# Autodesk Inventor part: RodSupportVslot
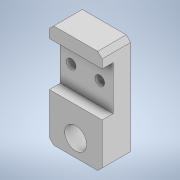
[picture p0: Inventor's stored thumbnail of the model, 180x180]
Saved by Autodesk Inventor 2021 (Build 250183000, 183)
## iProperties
Created: 2026-10
Part Number: RodSupportVslot
Material: Generic
Document SubType Name: Modeling
Designer: hp
Density: 1 g/cm^3
Appearance: Default
Author: hp
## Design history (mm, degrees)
sketch "Sketch1"
  geometry: L1 (72.236, 16.269)-(48.236, 16.269); L2 (72.236, 16.269)-(72.236, 36.369); L3 (48.236, 36.369)-(72.236, 36.369); L4 (48.236, 36.369)-(72.236, 36.369); L5 (72.236, 36.369)-(72.236, 40.319); L6 (70.236, 42.319)-(72.236, 40.319); L7 (70.236, 42.319)-(48.236, 42.319); L8 (48.236, 42.319)-(48.236, 36.369); L9 (72.236, 16.269)-(48.236, 16.269); L10 (48.236, 16.269)-(48.236, 10.319); L11 (48.236, 10.319)-(70.236, 10.319); L12 (72.236, 12.319)-(70.236, 10.319); L13 (72.236, 12.319)-(72.236, 16.269); L14 (48.236, 42.319)-(53.236, 42.319); L15 (53.236, 10.319)-(48.236, 10.319); L16 (48.236, 36.369)-(48.236, 16.269); L17 (48.236, 10.319)-(48.236, -4.681); L18 (48.236, -4.681)-(72.236, -4.681); L19 (72.236, -4.681)-(72.236, 12.319); C1 r 2.15 at (53.236, 26.319); C2 r 2.15 at (66.236, 26.319); C3 r 5 at (60.236, 3.063); 10 further points
  constraints: 38 end point, 3 centre point, 2 horizontal alignment, 2 midpoint, 2 perpendicular, 2 vertical
  dimensions: "d0" = 10 diameter of C3; "d1" = 23.256 vertical distance of C2.centre C3.centre; "d2" = 24 distance of L3.start L2.end; "d3" = 20.1 distance of L4.start L9.end; "d4" = 5.95 distance of L9.end L10.end; "d5" = 5.95 distance of L7.end L4.start; "d6" = 22 distance of L6.start L7.end; "d7" = 20.1 distance of L1.start L2.end; "d8" = 22 distance of L10.end L11.end; "d9" = 4.3 diameter of C1; "d10" = 4.3 diameter of C2; "d11" = 13 distance of C2.centre C1.centre; "d12" = 10.05 distance from line of L3 C1.centre; "d13" = 6 distance from line of L2 C2.centre; "d14" = 5 distance from line of L16 C1.centre; "d15" = 12 distance from line of L2 C3.centre; "d20" = 15 distance of L15.end L17.end; "d21" = 24 distance of L17.end L18.end
extrude "Extrusion1" new body sketch "Sketch1" distance "d16" = 8; taper "d17" = 0 deg
extrude "Extrusion2" join sketch "Sketch1" distance "d18" = 13; taper "d19" = 0 deg
chamfer "Chamfer1" distance "d22" = 2; stored, may be unused: second distance "d23" = 2, angle "d24" = 45 deg
body "Solid1"
